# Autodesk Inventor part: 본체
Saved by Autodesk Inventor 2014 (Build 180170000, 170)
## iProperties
Created: 2025-06
Part Number: 본체
Material: 알루미늄 6061
Document SubType Name: Modeling
Designer: dg
Density: 2.71 g/cm^3
Appearance: 알루미늄 - 평지
Mass: 806.366 g
Surface Area: 539.755 cm^2
Volume: 297.552 cm^3
Author: jhkim
Creation Date: 2025-05-27
Sending System: Autodesk Inventor 2026
Preprocessor: ST-DEVELOPER v20.1
Author: dg
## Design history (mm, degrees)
node "본체1"
node "솔리드1"
node "기준1"
